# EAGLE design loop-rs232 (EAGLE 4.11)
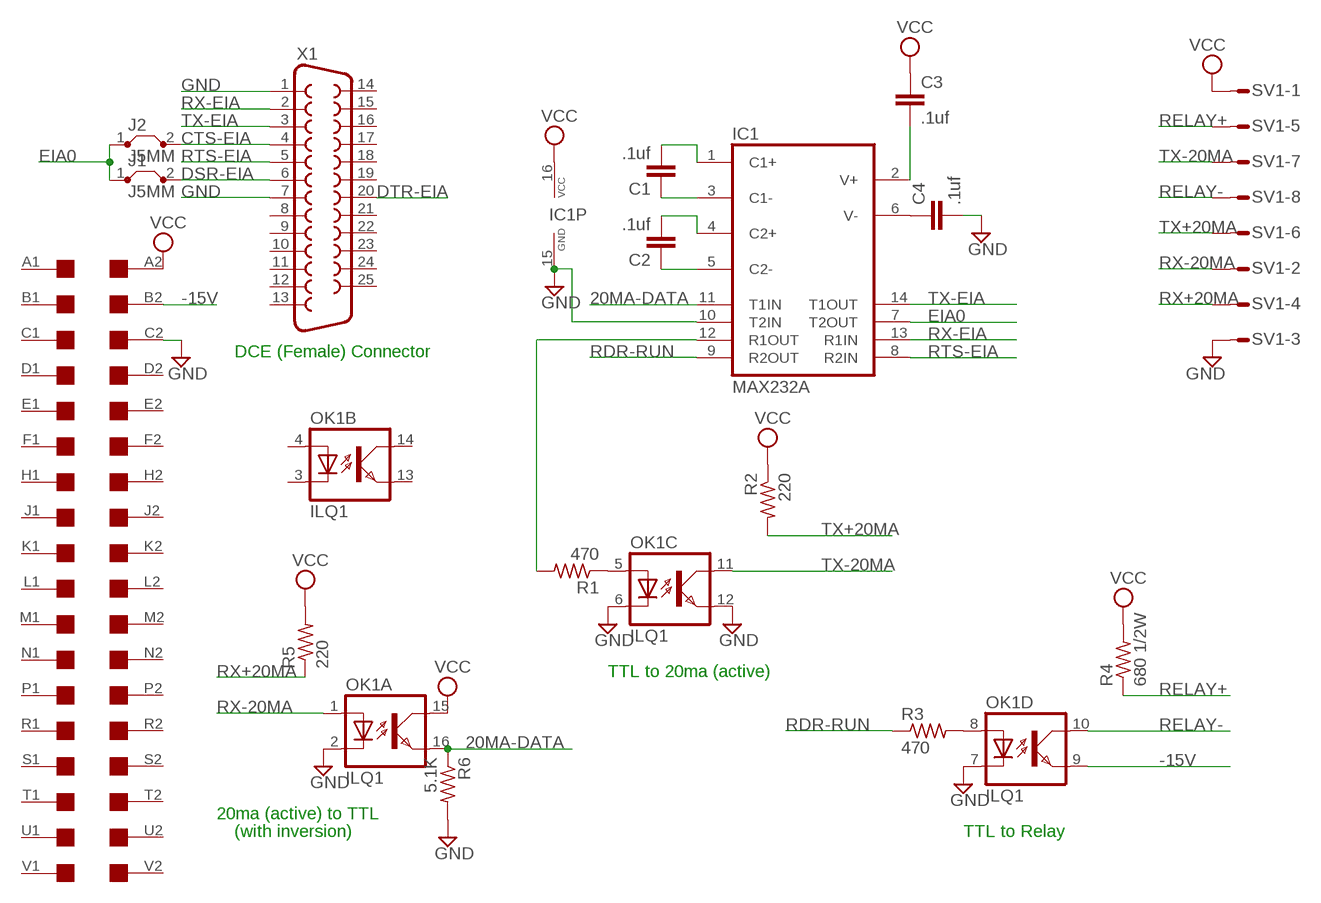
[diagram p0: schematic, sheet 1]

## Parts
C1  .1uf  C-EU050-025X075  [C050-025X075]
C2  .1uf  C-EU050-025X075  [C050-025X075]
C3  .1uf  C-EU050-025X075  [C050-025X075]
C4  .1uf  C-EU050-025X075  [C050-025X075]
IC1  MAX232A  MAX232  [DIL16]
J1  J5MM  [05]
J2  J5MM  [05]
OK1  ILQ1  [DIL16]
R1  470  R-US_0207/10  [0207/10]
R2  220  R-US_0207/10  [0207/10]
R3  470  R-US_0207/10  [0207/10]
R4  680 1/2W  R-US_0207/10  [0207/10]
R5  220  R-US_0207/10  [0207/10]
R6  5.1K  R-US_0207/10  [0207/10]
SV1  S08P  [S08P]
U$1  DEC-FLIPCHIP  [DEC-FLIPCHIP]
X1  F25H  [F25H]

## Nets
20MA-DATA: IC1.11(T1IN) OK1.16(A:EMIT) R6.1
-15V: OK1.9(D:EMIT) U$1.B2
CTS-EIA: J2.2 X1.4
DSR-EIA: J1.2 X1.6
DTR-EIA: X1.20
EIA0: IC1.7(T2OUT) J1.1 J2.1
EIA-DATA: OK1.5(C:A) R1.1
GND: C4.2 IC1.10(T2IN) IC1.15(GND) OK1.2(A:C) OK1.6(C:C) OK1.7(D:C) OK1.12(C:EMIT) R6.2 SV1.3 U$1.C2 X1.1 X1.7
N$1: C2.1 IC1.5(C2-)
N$2: C2.2 IC1.4(C2+)
N$3: C1.2 IC1.1(C1+)
N$4: C1.1 IC1.3(C1-)
N$8: IC1.12(R1OUT) R1.2
N$9: C3.2 IC1.2(V+)
N$10: C4.1 IC1.6(V-)
N$12: OK1.8(D:A) R3.2
RDR-RUN: IC1.9(R2OUT) R3.1
RELAY+: R4.1 SV1.5
RELAY-: OK1.10(D:COL) SV1.8
RTS-EIA: IC1.8(R2IN) X1.5
RX+20MA: R5.1 SV1.4
RX-20MA: OK1.1(A:A) SV1.2
RX-EIA: IC1.13(R1IN) X1.2
TX+20MA: R2.2 SV1.6
TX-20MA: OK1.11(C:COL) SV1.7
TX-EIA: IC1.14(T1OUT) X1.3
VCC: C3.1 IC1.16(VCC) OK1.15(A:COL) R2.1 R4.2 R5.2 SV1.1 U$1.A2
Unconnected: OK1.3(B:C) OK1.4(B:A) OK1.13(B:EMIT) OK1.14(B:COL) U$1.A1 U$1.B1 U$1.C1 U$1.D1 U$1.D2 U$1.E1 U$1.E2 U$1.F1 U$1.F2 U$1.H1 U$1.H2 U$1.J1 U$1.J2 U$1.K1 U$1.K2 U$1.L1 U$1.L2 U$1.M1 U$1.M2 U$1.N1 U$1.N2 U$1.P1 U$1.P2 U$1.R1 U$1.R2 U$1.S1 U$1.S2 U$1.T1 U$1.T2 U$1.U1 U$1.U2 U$1.V1 U$1.V2 X1.8 X1.9 X1.10 X1.11 X1.12 X1.13 X1.14 X1.15 X1.16 X1.17 X1.18 X1.19 X1.21 X1.22 X1.23 X1.24 X1.25

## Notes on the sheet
- DCE (Female) Connector
- TTL to 20ma (active)
- 20ma (active) to TTL
- (with inversion) | TTL to Relay

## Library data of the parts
C1-C4 = rcl:C-EU: CAPACITOR, European symbol
IC1 = maxim:MAX232: RS232 TRANSEIVER
J1 J2 = jumper:J: Bridge
OK1 = optocoupler:ILQ1: SIEMENS OPTO COUPLER
R1-R6 = rcl:R-US_: RESISTOR, American symbol
SV1 = con-amp-mt:S08P: AMP MT CONNECTOR
U$1 = con-dec:DEC-FLIPCHIP: DEC Flip-Chip single card fingers
X1 = con-subd:F25: SUB-D

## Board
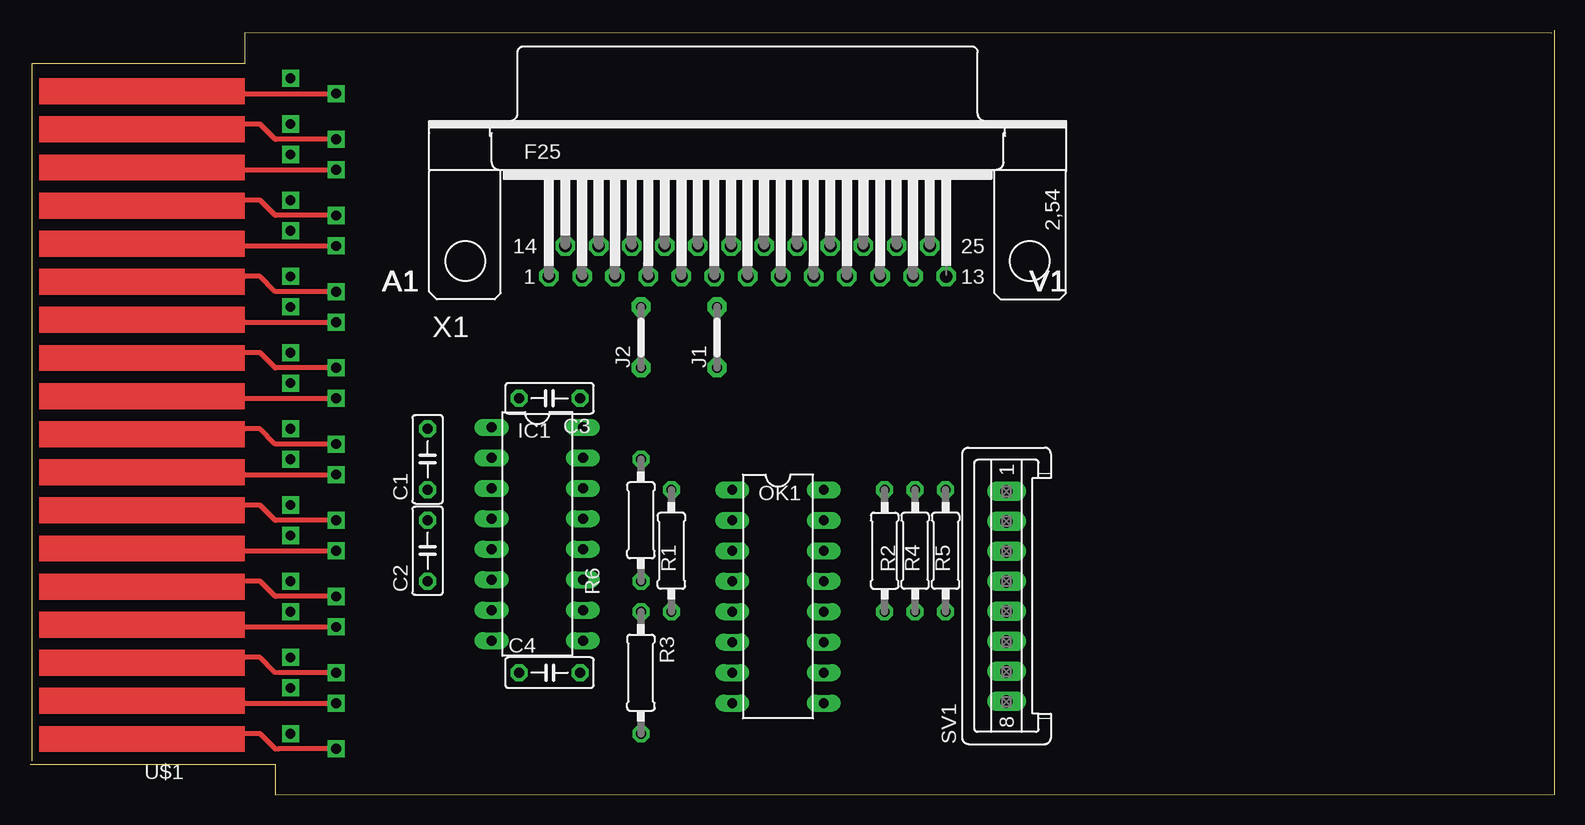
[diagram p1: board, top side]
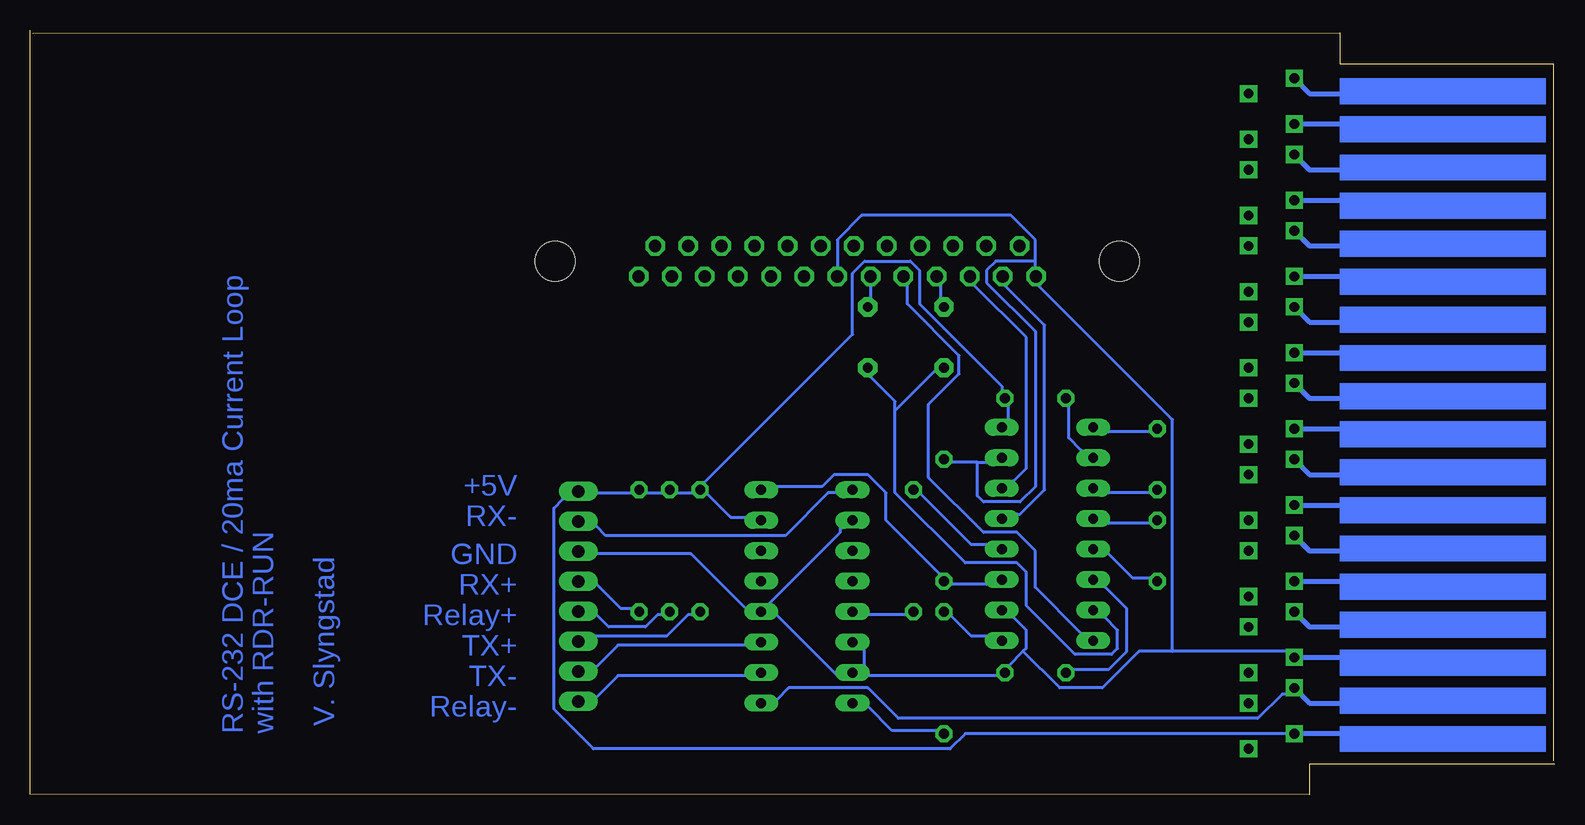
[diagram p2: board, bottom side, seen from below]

Size 127.11 x 63.72 mm. Coordinates in mm from the lower left corner, seen from the top.
Outline: 0,2.54 20.45,2.54 20.45,0 127.11,0.04 127.11,63.72
Outline: 126.87,63.46 17.91,63.5 17.91,60.92 0.13,60.92 0.13,2.83
Copper layers (1*16): Top 0.035mm / dielectric 1.5mm / Bottom 0.035mm
Design rules "10mils": minimum track width 10mil, minimum drill 28mil, track to track 15mil, track to pad 10mil, pad to pad 10mil, via to via 10mil, smd to smd 10mil, copper to edge 40mil, drill to drill 10mil, minimum pad ring 12mil, minimum via ring 8mil, stop-mask expansion 0mil, vias tented up to drill 0mil, thermal gap 10mil

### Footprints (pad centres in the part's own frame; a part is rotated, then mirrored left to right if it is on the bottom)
C050-025X075 = drill 0.813 octagon: 1 -2.54,0; 2 2.54,0
DIL16 = drill 0.813 long: 1 -8.89,-3.81; 2 -6.35,-3.81; 3 -3.81,-3.81; 4 -1.27,-3.81; 5 1.27,-3.81; 6 3.81,-3.81; 7 6.35,-3.81; 8 8.89,-3.81; 9 8.89,3.81; 10 6.35,3.81; 11 3.81,3.81; 12 1.27,3.81; 13 -1.27,3.81; 14 -3.81,3.81; 15 -6.35,3.81; 16 -8.89,3.81
05 = drill 0.813 pad 1.6 octagon: 1 -2.54,0; 2 2.54,0
0207/10 = drill 0.813 octagon: 1 -5.08,0; 2 5.08,0
S08P = drill 1.016 long: 1 8.75,0; 2 6.25,0; 3 3.75,0; 4 1.25,0; 5 -1.25,0; 6 -3.75,0; 7 -6.25,0; 8 -8.75,0
DEC-FLIPCHIP = drill 0.813 square: A1 -7.62,27.94; A2 -3.81,26.67; B1 -7.62,24.13; B2 -3.81,22.86; C1 -7.62,21.59; C2 -3.81,20.32; D1 -7.62,17.78; D2 -3.81,16.51; E1 -7.62,15.24; E2 -3.81,13.97; F1 -7.62,11.43; F2 -3.81,10.16; H1 -7.62,8.89; H2 -3.81,7.62; J1 -7.62,5.08; J2 -3.81,3.81; K1 -7.62,2.54; K2 -3.81,1.27; L1 -7.62,-1.27; L2 -3.81,-2.54; M1 -7.62,-3.81; M2 -3.81,-5.08; N1 -7.62,-7.62; N2 -3.81,-8.89; P1 -7.62,-10.16; P2 -3.81,-11.43; R1 -7.62,-13.97; R2 -3.81,-15.24; S1 -7.62,-16.51; S2 -3.81,-17.78; T1 -7.62,-20.32; T2 -3.81,-21.59; U1 -7.62,-22.86; U2 -3.81,-24.13; V1 -7.62,-26.67; V2 -3.81,-27.94
F25H = drill 1.016 octagon: 1 -16.561,-1.27; 2 -13.792,-1.27; 3 -11.049,-1.27; 4 -8.28,-1.27; 5 -5.512,-1.27; 6 -2.769,-1.27; 7 0,-1.27; 8 2.769,-1.27; 9 5.512,-1.27; 10 8.28,-1.27; 11 11.049,-1.27; 12 13.792,-1.27; 13 16.561,-1.27; 14 -15.189,1.27; 15 -12.421,1.27; 16 -9.652,1.27; 17 -6.909,1.27; 18 -4.14,1.27; 19 -1.372,1.27; 20 1.372,1.27; 21 4.14,1.27; 22 6.909,1.27; 23 9.652,1.27; 24 12.421,1.27; 25 15.189,1.27 | hole 3.302: -23.52,0; 23.52,0

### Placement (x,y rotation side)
C1  33.15,27.94 90 top
C2  33.15,20.32 90 top
C3  43.31,33.02 180 top
C4  43.31,10.16 0 top
IC1  42.29,21.72 270 top
J1  57.28,38.1 90 top
J2  50.93,38.1 90 top
OK1  62.36,16.51 270 top
R1  53.47,20.32 90 top
R2  71.25,20.32 270 top
R3  50.93,10.16 270 top
R4  73.79,20.32 90 top
R5  76.33,20.32 90 top
R6  50.93,22.86 90 top
SV1  81.41,16.51 90 top
U$1  17.91,31.75 180 top
X1  59.82,44.45 0 top

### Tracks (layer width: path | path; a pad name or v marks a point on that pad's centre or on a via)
20MA-DATA
  Bottom 0.254: IC1.11 47.37,17.53 50.42,17.53 R6.1 51.18,18.29 55.75,22.86 55.75,25.15 57.28,26.67 60.07,26.67 61.09,25.65 64.9,25.65 OK1.16
-15V
  Bottom 0.254: U$1.B2 22.22,8.38 22.73,8.38 24.77,6.35 54.74,6.35 57.28,8.89 63.88,8.89 64.9,7.87 OK1.9
CTS-EIA
  Bottom 0.254: J2.2 51.18,41.4 51.18,42.42 X1.4
DSR-EIA
  Bottom 0.254: J1.2 57.02,41.4 57.02,42.42 X1.6
EIA0
  Bottom 0.254: 54.99,32 54.99,32.77 57.02,34.8 J1.1 | 54.99,32 54.99,25.15 49.15,19.3 44.83,19.3 44.07,18.54 44.07,15.75 40.01,11.68 36.96,11.68 36.45,12.19 36.45,13.72 37.47,14.73 IC1.7 | 54.99,32 51.69,35.31 J2.1
EIA-DATA
  Bottom 0.254: R1.1 53.98,14.99 57.28,14.99 OK1.5
GND
  Bottom 0.254: 48.13,27.69 47.37,27.69 IC1.15 | 48.13,27.69 50.42,27.69 R6.2 | 43.31,44.45 43.31,46.23 45.34,48.26 57.79,48.26 59.82,46.23 X1.7 | 43.31,44.45 43.31,43.94 X1.1 43.05,42.42 31.88,31.24 31.88,11.94 | 48.13,27.69 48.13,24.89 47.62,24.38 44.58,24.38 43.31,25.65 43.31,38.61 47.37,42.67 47.37,43.69 46.61,44.45 43.31,44.45 | 44.32,11.94 44.07,12.19 44.07,13.72 45.09,14.73 IC1.10 | 44.32,11.94 45.59,10.67 C4.2 46.36,9.91 57.28,9.91 OK1.7 | 31.88,11.94 34.67,11.94 37.72,8.89 41.28,8.89 44.32,11.94 | 31.88,11.94 22.22,11.94 U$1.C2 | OK1.7 57.53,10.67 57.53,12.19 OK1.6 | OK1.12 64.9,14.99 59.82,9.91 OK1.7 | OK1.2 59.56,22.35 59.56,21.84 OK1.12 | SV1.3 79.88,20.07 72.01,20.07 67.44,15.49 OK1.12
N$1
  Bottom 0.254: C2.1 33.66,18.03 35.18,18.03 37.21,20.07 IC1.5
N$2
  Bottom 0.254: C2.2 33.66,22.61 37.21,22.61 IC1.4
N$3
  Bottom 0.254: C1.2 33.66,30.23 37.21,30.23 IC1.1
N$4
  Bottom 0.254: C1.1 33.66,25.15 37.21,25.15 IC1.3
N$8
  Bottom 0.254: IC1.12 47.37,20.83 48.64,20.83 52.96,25.15 R1.2
N$9
  Bottom 0.254: IC1.2 39.5,28.7 40.51,29.72 40.51,32.51 C3.2
N$10
  Bottom 0.254: C4.1 40.26,10.41 37.21,10.41 35.69,11.94 35.69,15.49 37.47,17.27 IC1.6
N$12
  Bottom 0.254: R3.2 51.44,5.33 55.25,5.33 57.28,7.37 OK1.8
RDR-RUN
  Bottom 0.254: IC1.9 47.37,13.21 48.64,13.21 50.42,14.99 R3.1
RELAY+
  Bottom 0.254: R4.1 74.3,14.99 74.8,14.99 75.82,13.97 78.87,13.97 79.88,14.99 SV1.5
RELAY-
  Bottom 0.254: OK1.10 67.44,9.91 78.1,9.91 79.88,8.13 SV1.8
RTS-EIA
  Bottom 0.254: IC1.8 39.5,13.46 43.31,17.27 43.31,20.32 44.83,21.84 47.62,21.84 52.2,26.42 52.2,32.51 49.66,35.05 49.66,36.58 53.98,40.89 53.98,42.42 X1.5
RX+20MA
  Bottom 0.254: R5.1 76.83,15.49 77.85,15.49 79.88,17.53 SV1.4
RX-20MA
  Bottom 0.254: OK1.1 59.82,25.15 60.58,25.15 64.13,21.59 79.12,21.59 79.88,22.35 SV1.2
RX-EIA
  Bottom 0.254: IC1.13 44.83,23.37 44.58,23.37 42.55,25.4 42.55,39.12 45.85,42.42 X1.2
TX+20MA
  Bottom 0.254: R2.2 71.75,14.99 72.26,14.99 74.04,13.21 80.14,13.21 SV1.6
TX-20MA
  Bottom 0.254: OK1.11 67.44,12.45 78.1,12.45 79.88,10.67 SV1.7
TX-EIA
  Bottom 0.254: IC1.14 45.09,26.16 44.07,27.18 44.07,38.1 48.39,42.42 X1.3
VCC
  Bottom 0.254: IC1.16 45.59,31.24 45.59,32.51 C3.1 46.1,33.53 46.1,34.04 52.96,40.89 52.96,43.69 53.72,44.45 57.53,44.45 58.55,43.43 58.55,38.35 70.99,25.91 R2.1 | OK1.15 67.44,23.11 68.71,23.11 70.74,25.15 R2.1 | R2.1 71.75,25.15 73.28,25.15 R4.2 74.3,25.15 75.82,25.15 R5.2 76.83,25.15 79.88,25.15 SV1.1 82.68,24.64 83.44,23.88 83.44,7.11 80.14,3.81 50.42,3.81 49.15,5.08 U$1.A2

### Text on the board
Bottom: +5V | RX- | GND | RX+ | Relay+ | TX+ | TX- | Relay- | V. Slyngstad | with RDR-RUN | RS-232 DCE / 20ma Current Loop
tNames: A1 | A1 | A1 | A1 | A1 | A1 | A1 | A1 | A1 | A1 | A1 | A1 | A1 | A1 | A1 | A1 | A1 | A1 | A1 | A1 | A1 | A1 | A1 | A1 | A1 | A1 | A1 | A1 | A1 | A1 | A1 | A1 | V1 | V1 | V1 | V1 | V1 | V1 | V1 | V1 | V1 | V1 | V1 | V1 | V1 | V1 | V1 | V1 | V1 | V1 | V1 | V1 | V1 | V1 | V1 | V1 | V1 | V1 | V1 | V1 | V1 | V1 | V1 | V1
